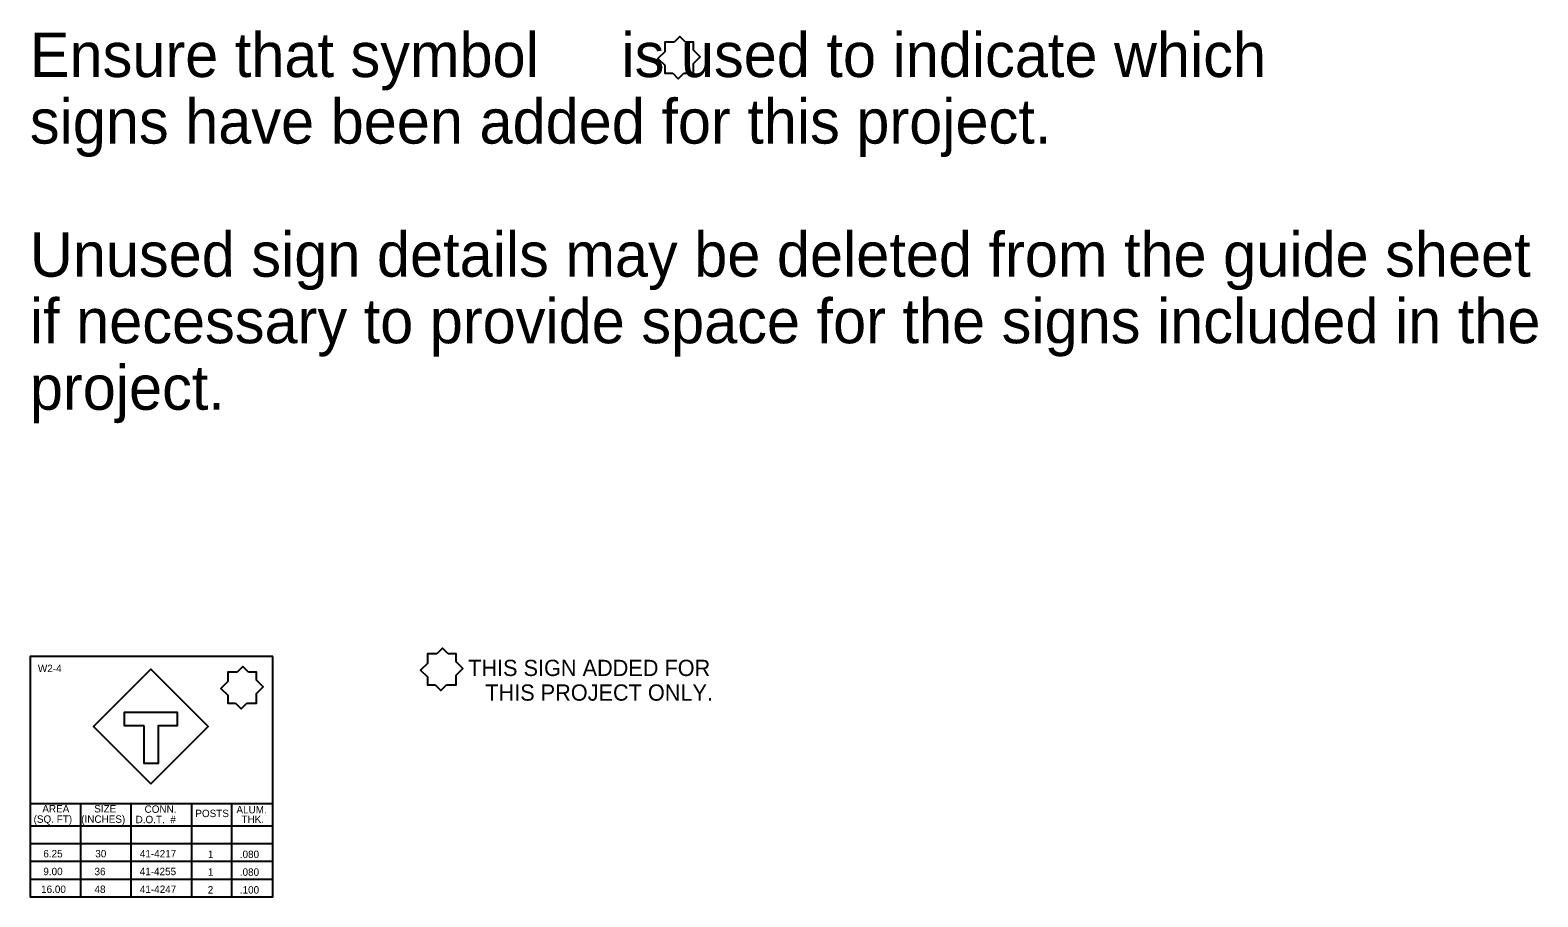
# Model space of a CAD drawing. Extents: x 0 to 2011, y -22 to 1183.
# Drawn here: x 1349 to 2000, y 24 to 398 of the extents above; entities that cross this region are included whole.
import ezdxf

# ---------------------------------------------------------------- set-up
doc = ezdxf.new("R2010")
doc.units = 0
for name, color, linetype in [('CT_Locked', 7, 'Continuous'), ('CT_TSH_Annotation_Border_Version', 7, 'Continuous'), ('Level 1', 7, 'Continuous'), ('Level 10', 7, 'Continuous'), ('Level 2', 7, 'Continuous'), ('Level 5', 7, 'Continuous')]:
    doc.layers.add(name, color=color, linetype=linetype)

msp = doc.modelspace()

# ---------------------------------------------------------------- linework, layer by layer
at = {"layer": 'CT_Locked'}
for points in [[(1627.46, 392.97), (1623.33, 392.97), (1623.33, 388.85)], [(1632.31, 392.97), (1629.88, 395.4), (1627.46, 392.97)], [(1635.74, 389.54), (1635.74, 392.97), (1632.31, 392.97)], [(1623.33, 388.85), (1620.41, 385.93), (1623.33, 383.01)], [(1635.74, 383.7), (1638.66, 386.62), (1635.74, 389.54)], [(1623.33, 383.01), (1623.33, 379.58), (1626.76, 379.58)], [(1626.76, 379.58), (1629.19, 377.15), (1631.61, 379.58)], [(1631.61, 379.58), (1635.74, 379.58), (1635.74, 383.7)], [(1529.83, 129.09), (1527.4, 131.51), (1524.98, 129.09)], [(1520.85, 124.96), (1517.93, 122.04), (1520.85, 119.12)], [(1524.98, 129.09), (1520.85, 129.09), (1520.85, 124.96)], [(1533.26, 125.65), (1533.26, 129.09), (1529.83, 129.09)], [(1533.26, 119.82), (1536.18, 122.74), (1533.26, 125.65)], [(1438.75, 121.2), (1434.62, 121.2), (1434.62, 117.08)], [(1443.6, 121.2), (1441.17, 123.63), (1438.75, 121.2)], [(1447.03, 117.77), (1447.03, 121.2), (1443.6, 121.2)], [(1447.03, 111.93), (1449.95, 114.85), (1447.03, 117.77)], [(1520.85, 119.12), (1520.85, 115.69), (1524.28, 115.69)], [(1529.13, 115.69), (1533.26, 115.69), (1533.26, 119.82)], [(1434.62, 117.08), (1431.7, 114.16), (1434.62, 111.24)], [(1434.62, 111.24), (1434.62, 107.81), (1438.05, 107.81)], [(1442.91, 107.81), (1447.03, 107.81), (1447.03, 111.93)], [(1524.28, 115.69), (1526.71, 113.26), (1529.13, 115.69)], [(1438.05, 107.81), (1440.48, 105.38), (1442.91, 107.81)]]:
    msp.add_lwpolyline(points, dxfattribs=at)
at = {"layer": 'Level 1'}
msp.add_lwpolyline([(1398.57, 97.96), (1390.14, 97.96), (1390.14, 103.96), (1412.81, 103.96), (1412.81, 97.96), (1404.57, 97.96), (1404.57, 81.75), (1398.57, 81.75)], close=True, dxfattribs=at)
at = {"layer": 'Level 2'}
for p, q in [((1349.34, 64.53), (1454.09, 64.53)), ((1371.09, 64.53), (1371.09, 24.25)), ((1392.84, 64.53), (1392.84, 24.25)), ((1418.94, 64.53), (1418.94, 24.25)), ((1436.34, 64.53), (1436.34, 24.25)), ((1349.34, 54.94), (1454.09, 54.94)), ((1349.34, 47.27), (1454.09, 47.27)), ((1349.34, 39.6), (1454.09, 39.6)), ((1349.34, 31.93), (1454.09, 31.93))]:
    msp.add_line(p, q, dxfattribs=at)
for points in [[(1454.09, 127.88), (1349.34, 127.88), (1349.34, 24.25), (1454.09, 24.25)], [(1401.43, 72.97), (1426.18, 97.72), (1401.43, 122.46), (1376.68, 97.72)]]:
    msp.add_lwpolyline(points, close=True, dxfattribs=at)

# ---------------------------------------------------------------- texts
at = {"layer": 'CT_TSH_Annotation_Border_Version'}
for s, p in [('Ensure that symbol     is used to indicate which ', (1349.22, 377.92)), ('signs have been added for this project.', (1349.22, 349.21)), ('Unused sign details may be deleted from the guide sheet', (1349.22, 291.79)), ('if necessary to provide space for the signs included in the ', (1349.22, 263.08)), ('project.', (1349.22, 234.38))]:
    msp.add_text(s, height=19.2, dxfattribs=at).set_placement(p)
at = {"layer": 'Level 10'}
for s, p in [('THIS SIGN ADDED FOR', (1538.45, 119.51)), ('THIS PROJECT ONLY.', (1545.85, 108.88))]:
    msp.add_text(s, height=7, dxfattribs=at).set_placement(p)
at = {"layer": 'Level 2'}
for s, p in [('W2-4', (1352.69, 121.18)), ('(SQ. FT)', (1350.83, 56.18)), ('AREA', (1354.61, 60.65)), ('(INCHES)', (1371.39, 56.18)), ('SIZE', (1377.02, 60.65)), ('D.O.T.  #', (1394.87, 56.02)), ('CONN.', (1398.74, 60.49)), ('POSTS', (1420.66, 58.64)), ('ALUM.', (1438.4, 60.27)), ('THK.', (1440.58, 56.13))]:
    msp.add_text(s, height=3.2, dxfattribs=at).set_placement(p)
at = {"layer": 'Level 5'}
for s, p in [(' 6.25', (1353.84, 41.26)), ('  30 ', (1375.1, 41.26)), ('41-4217', (1396.71, 41.26)), ('1', (1426.08, 41)), ('.080', (1439.86, 41)), (' 9.00', (1353.84, 33.59)), ('  36 ', (1374.75, 33.59)), ('41-4255', (1396.65, 33.59)), ('1', (1426.08, 33.33)), ('.080', (1439.86, 33.33)), ('16.00', (1354.06, 25.92)), ('  48 ', (1374.75, 25.92)), ('41-4247', (1396.71, 25.92)), ('2', (1426.02, 25.66)), ('.100', (1439.86, 25.66))]:
    msp.add_text(s, height=3.2, dxfattribs=at).set_placement(p)

doc.saveas('drawing.dxf')
